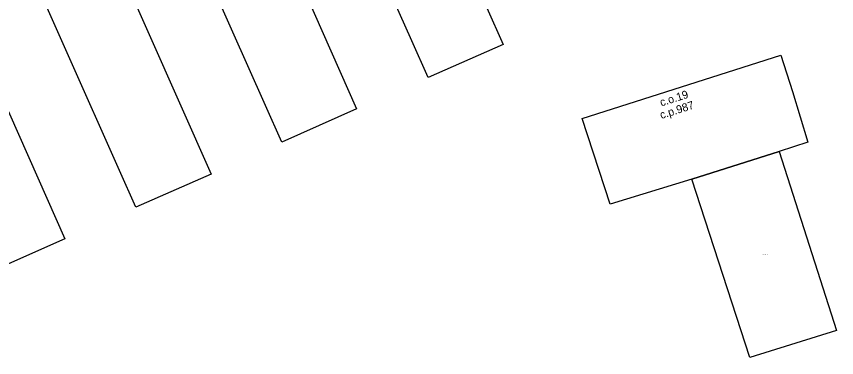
# Model space of a CAD drawing. Extents: x -600391 to -599491, y -1160176 to -1159402.
# Drawn here: x -599605.2 to -599502.6, y -1159660.6 to -1159617.9 of the extents above; entities that cross this region are included whole.
import ezdxf

# ---------------------------------------------------------------- set-up
doc = ezdxf.new("R2010")
doc.units = 0
for name, color, linetype in [('Level 10', 7, 'Continuous'), ('Level 12', 7, 'Continuous'), ('Level 25', 7, 'Continuous'), ('Level 61', 7, 'Continuous'), ('Level 62', 7, 'Continuous')]:
    doc.layers.add(name, color=color, linetype=linetype)

msp = doc.modelspace()

# ---------------------------------------------------------------- linework, layer by layer
at = {"layer": 'Level 61'}
for points in [[(-599555.73, -1159621), (-599581.32, -1159563.75)], [(-599590.07, -1159567.49), (-599562.63, -1159629.51)], [(-599574.03, -1159629.08), (-599599.51, -1159571.8)], [(-599608.4, -1159575.57), (-599580.81, -1159637.66)], [(-599592.26, -1159637.21), (-599617.83, -1159579.82)], [(-599626.66, -1159583.6), (-599599.1, -1159645.74)], [(-599546.34, -1159616.86), (-599544.32, -1159621.44)], [(-599553.71, -1159625.58), (-599555.73, -1159621)], [(-599544.32, -1159621.44), (-599553.71, -1159625.58)], [(-599534.44, -1159630.71), (-599509.61, -1159622.79)], [(-599509.61, -1159622.79), (-599508.14, -1159627.34)], [(-599508.14, -1159627.34), (-599506.23, -1159633.64)], [(-599571.99, -1159633.66), (-599574.03, -1159629.08)], [(-599562.63, -1159629.51), (-599571.99, -1159633.66)], [(-599530.95, -1159641.41), (-599534.44, -1159630.71)], [(-599506.23, -1159633.64), (-599509.8, -1159634.83)], [(-599509.8, -1159634.83), (-599520.72, -1159638.28)], [(-599520.72, -1159638.28), (-599509.8, -1159634.83)], [(-599509.8, -1159634.83), (-599502.64, -1159657.2)], [(-599590.22, -1159641.78), (-599592.26, -1159637.21)], [(-599580.81, -1159637.66), (-599590.22, -1159641.78)], [(-599520.72, -1159638.28), (-599530.95, -1159641.41)], [(-599513.47, -1159660.58), (-599520.72, -1159638.28)], [(-599599.1, -1159645.74), (-599608.46, -1159649.85)], [(-599502.64, -1159657.2), (-599513.47, -1159660.58)]]:
    msp.add_lwpolyline(points, dxfattribs=at)
at = {"layer": 'Level 62'}
for points in [[(-599549.27, -1159610.28), (-599546.34, -1159616.86), (-599544.32, -1159621.44), (-599553.71, -1159625.58), (-599555.73, -1159621), (-599581.32, -1159563.75), (-599581.04, -1159563.62), (-599571.97, -1159559.29), (-599549.27, -1159610.28)], [(-599574.03, -1159629.08), (-599599.51, -1159571.8), (-599599.01, -1159571.57), (-599590.07, -1159567.49), (-599562.63, -1159629.51), (-599571.99, -1159633.66), (-599574.03, -1159629.08)], [(-599580.81, -1159637.66), (-599590.22, -1159641.78), (-599592.26, -1159637.21), (-599617.83, -1159579.82), (-599608.4, -1159575.57), (-599580.81, -1159637.66)], [(-599610.49, -1159645.3), (-599636.09, -1159588), (-599626.66, -1159583.6), (-599599.1, -1159645.74), (-599608.46, -1159649.85), (-599610.49, -1159645.3)], [(-599520.72, -1159638.28), (-599530.95, -1159641.41), (-599534.44, -1159630.71), (-599509.61, -1159622.79), (-599508.14, -1159627.34), (-599506.23, -1159633.64), (-599509.8, -1159634.83), (-599520.72, -1159638.28)], [(-599520.72, -1159638.28), (-599509.8, -1159634.83), (-599502.64, -1159657.2), (-599513.47, -1159660.58), (-599520.72, -1159638.28)]]:
    msp.add_lwpolyline(points, dxfattribs=at)

# ---------------------------------------------------------------- texts
at = {"layer": 'Level 10'}
msp.add_text('c.o.19', height=1, rotation=17.6921, dxfattribs=at).set_placement((-599524.55, -1159629.2))
at = {"layer": 'Level 12'}
msp.add_text('c.p.987', height=1, rotation=17.6921, dxfattribs=at).set_placement((-599524.55, -1159630.77))
at = {"layer": 'Level 25'}
msp.add_text('c.pp.987_B', height=0.1, dxfattribs=at).set_placement((-599511.96, -1159647.73))

doc.saveas('drawing.dxf')
